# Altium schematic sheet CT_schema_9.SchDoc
size 274 x 160 mm
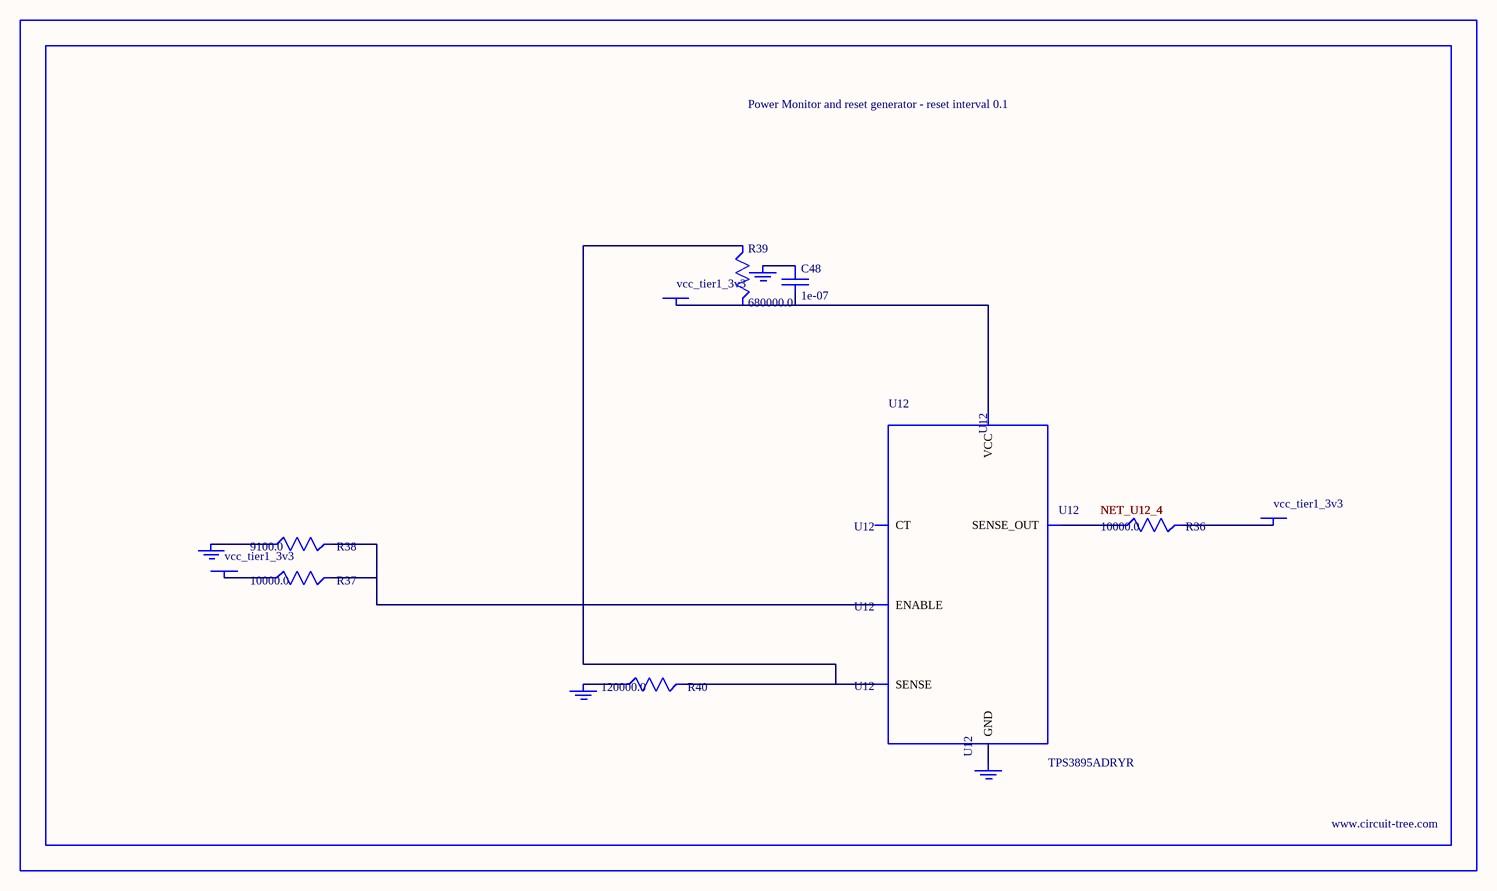
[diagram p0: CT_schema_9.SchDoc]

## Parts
BORDER8  (no value)
C48  1e-07  [C0402]
GND_INSTANCE_8_0  (no value)
GND_INSTANCE_8_1  (no value)
GND_INSTANCE_8_2  (no value)
GND_INSTANCE_8_3  (no value)
POWER_INSTANCE_8_0  vcc_tier1_3v3
POWER_INSTANCE_8_1  vcc_tier1_3v3
POWER_INSTANCE_8_2  vcc_tier1_3v3
R36  10000.0  [R0603]
R37  10000.0  [R0603]
R38  9100.0  [R0603]
R39  680000.0  [R0603]
R40  120000.0  [R0603]
U12  TPS3895ADRYR  [SON-6]

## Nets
NetC48_1: C48.1 GND_INSTANCE_8_2.0(GND)
NetC48_2: C48.2 POWER_INSTANCE_8_2.0(PWR) R39.2 U12.6(VCC)
NetGND_INSTANCE_8_0_0: GND_INSTANCE_8_0.0(GND) R38.1
NetGND_INSTANCE_8_1_0: GND_INSTANCE_8_1.0(GND) R40.1
NetGND_INSTANCE_8_3_0: GND_INSTANCE_8_3.0(GND) U12.2(GND)
NetPOWER_INSTANCE_8_0_0: POWER_INSTANCE_8_0.0(PWR) R37.1
NetPOWER_INSTANCE_8_1_0: POWER_INSTANCE_8_1.0(PWR) R36.2
NetR36_1: R36.1 U12.4(SENSE_OUT)
NetR37_2: R37.2 R38.2 U12.1(ENABLE)
NetR39_1: R39.1 R40.2 U12.3(SENSE)

Not connected (* = marked no-connect by the designer): U12 5(CT)

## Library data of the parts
BORDER8 = BORDER_PAGE8
C48 = C0402C104K3RACTU
GND_INSTANCE_8_0-GND_INSTANCE_8_3 = GND
POWER_INSTANCE_8_0-POWER_INSTANCE_8_2 = PWR
R36 R37 = RC0603JR-0710KL
R38 = RC0603JR-079K1L
R39 = RC0603JR-07680KL
R40 = RC0603JR-07120KL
